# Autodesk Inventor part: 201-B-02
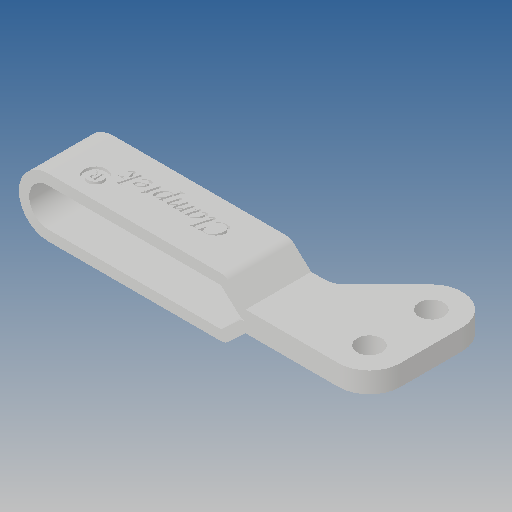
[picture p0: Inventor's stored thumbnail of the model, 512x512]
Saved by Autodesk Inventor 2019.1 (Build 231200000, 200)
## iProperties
Created: 2012-01
Part Number: 201-B-02
Material: Ogólny
Document SubType Name: Modeling
Designer: CADENGINEERING4
Density: 1 g/cm^3
Appearance: Domyślna
Author: CADENGINEERING4
Revision Number: ÈÎºÎ
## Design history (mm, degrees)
feature "ÇÐ³ý-À­Éì4"
node "Bryła1"
